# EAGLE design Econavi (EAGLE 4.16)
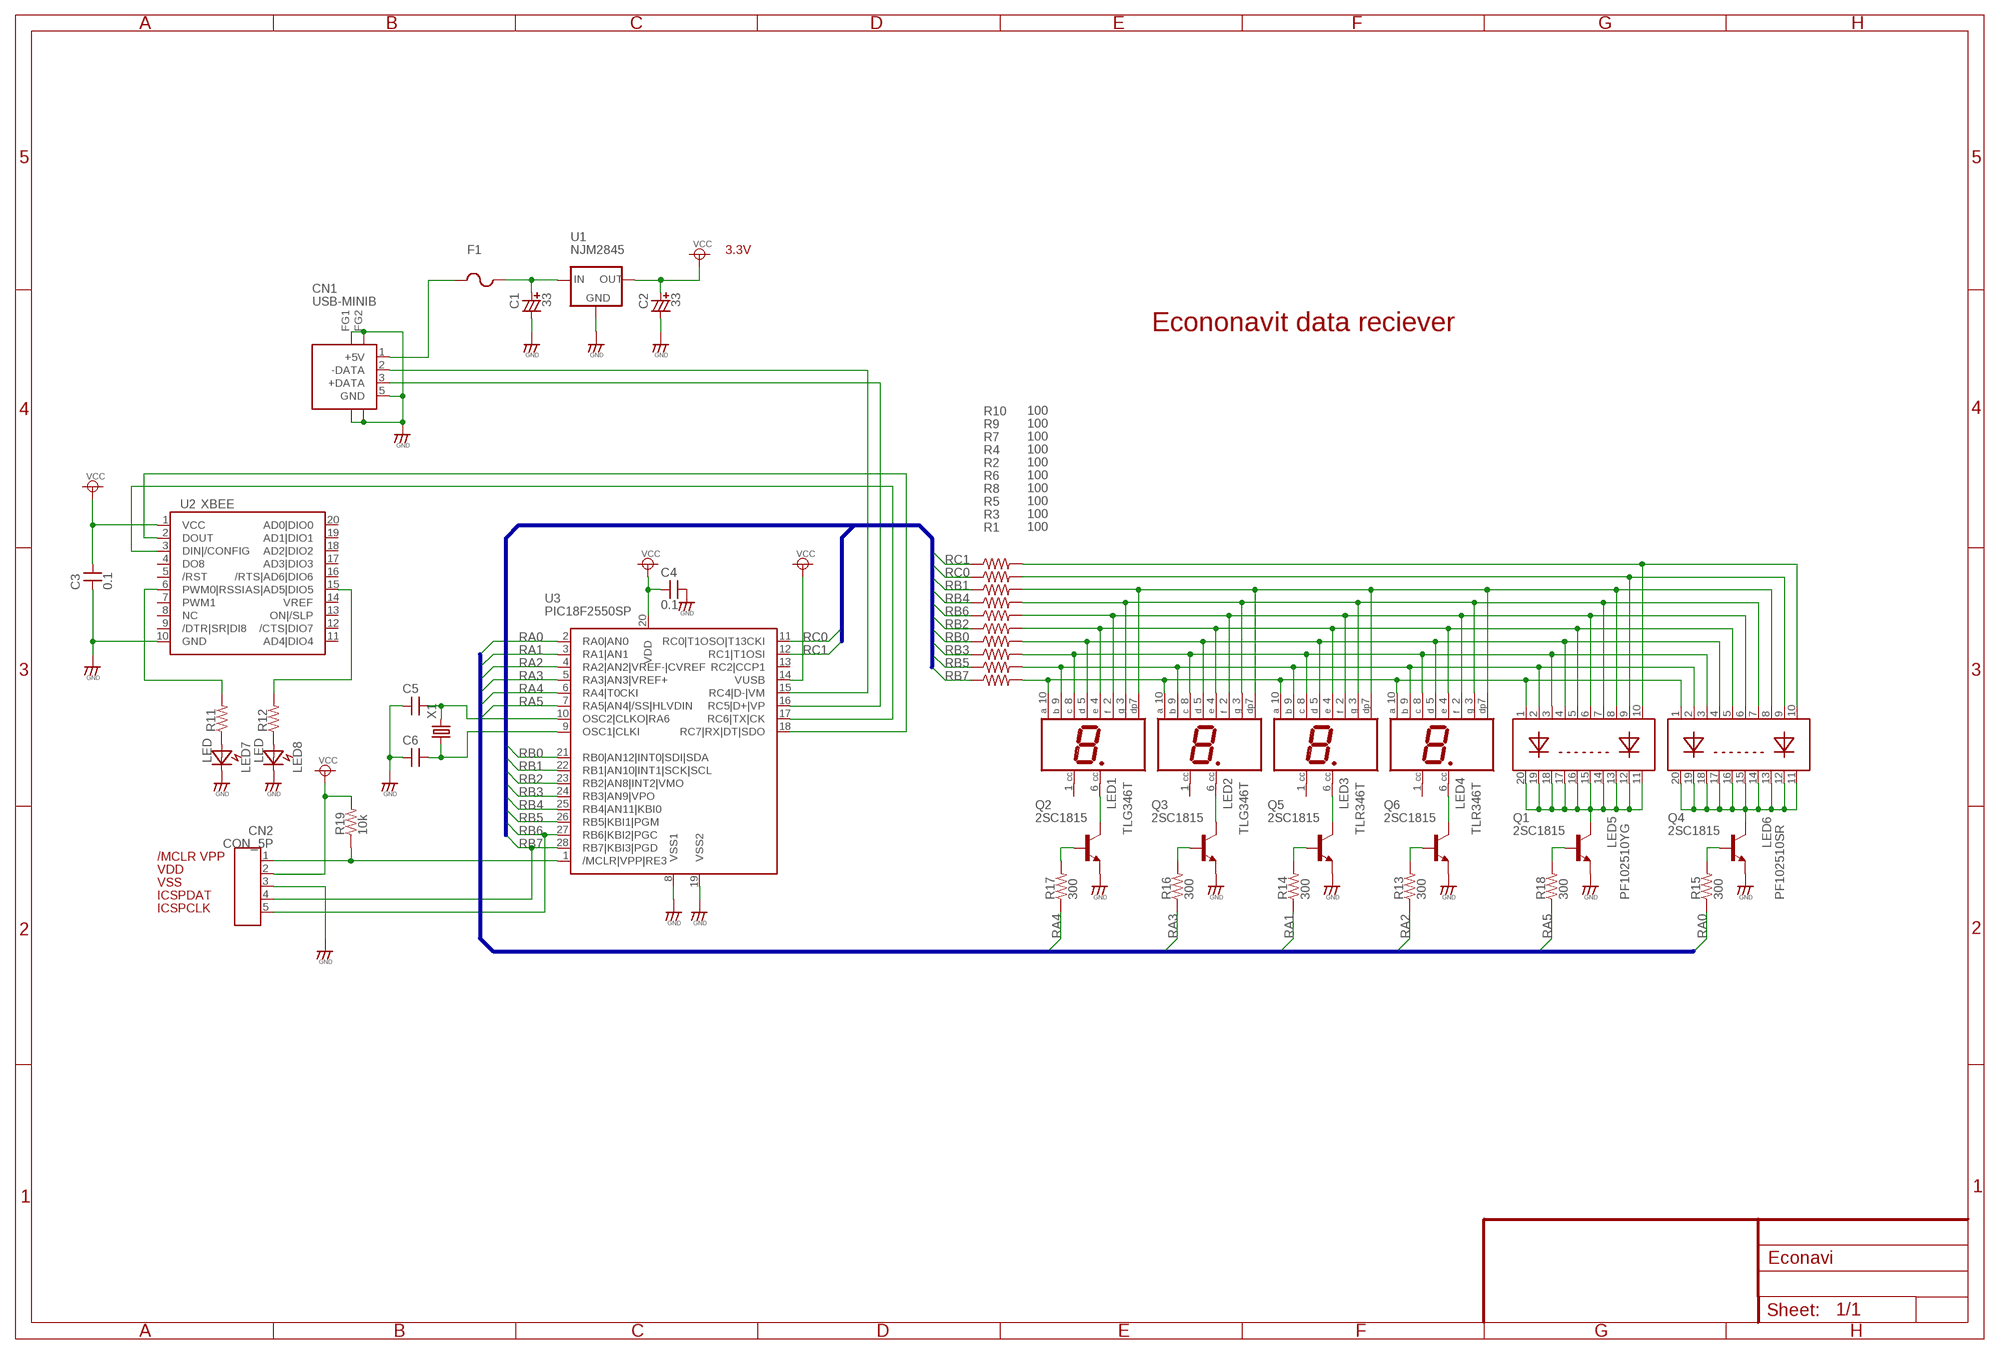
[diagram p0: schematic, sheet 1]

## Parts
C1  33  CCAPSMD3528  [CT3528]
C2  33  CCAPSMD3528  [CT3528]
C3  0.1  CAPSM2012  [C2012]
C4  0.1  CAPSM2012  [C2012]
C5  CAPDIP_1  [CAP_DIP_1]
C6  CAPDIP_1  [CAP_DIP_1]
CN1  USB-MINIB  [MINI-USB-B]
CN2  CON_5P  [CON_HDR_SIP5]
F1  POLYSW8X2MM  [AX_08X02_2P_200]
LED1  TLG346T  [4-10D1]
LED2  TLG346T  [4-10D1]
LED3  TLR346T  [4-10D1]
LED4  TLR346T  [4-10D1]
LED5  PF102510YG  PF102510  [LED10BAR]
LED6  PF102510SR  PF102510  [LED10BAR]
LED7  LED  [LED_3MM_VIRT_2]
LED8  LED  [LED_3MM_VIRT_2]
Q1  2SC1815  [TO92]
Q2  2SC1815  [TO92]
Q3  2SC1815  [TO92]
Q4  2SC1815  [TO92]
Q5  2SC1815  [TO92]
Q6  2SC1815  [TO92]
R1  100  R0.125W_2P  [R_0.125W_2]
R2  100  R0.125W_2P  [R_0.125W_2]
R3  100  R0.125W_2P  [R_0.125W_2]
R4  100  R0.125W_2P  [R_0.125W_2]
R5  100  R0.125W_2P  [R_0.125W_2]
R6  100  R0.125W_2P  [R_0.125W_2]
R7  100  R0.125W_2P  [R_0.125W_2]
R8  100  R0.125W_2P  [R_0.125W_2]
R9  100  R0.125W_2P  [R_0.125W_2]
R10  100  R0.125W_2P  [R_0.125W_2]
R11  R0.125W_2P  [R_0.125W_2]
R12  R0.125W_2P  [R_0.125W_2]
R13  300  R0.125W_2P  [R_0.125W_2]
R14  300  R0.125W_2P  [R_0.125W_2]
R15  300  R0.125W_2P  [R_0.125W_2]
R16  300  R0.125W_2P  [R_0.125W_2]
R17  300  R0.125W_2P  [R_0.125W_2]
R18  300  R0.125W_2P  [R_0.125W_2]
R19  10k  R0.125W_2P  [R_0.125W_2]
U1  NJM2845  [TO252]
U2  XBEE  [XBEE]
U3  PIC18F2550SP  [DIL28]
X1  CRYSTALHC49S  [HC49/S]

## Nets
DVCC: C2.+ C3.2 C4.1 CN2.2 R19.2 U1.3(OUT) U2.1(VCC) U3.14(VUSB) U3.20(VDD) ; supply symbol labelled VCC
GND: C1.- C2.- C3.1 C4.2 C5.1 C6.1 CN1.5(GND) CN1.FG1 CN1.FG2 CN1.FG3 CN1.FG4 CN2.3 LED7.K LED8.K Q1.E Q2.E Q3.E Q4.E Q5.E Q6.E U1.2(GND) U2.10(GND) U3.8(VSS1) U3.19(VSS2)
LED50: LED6.11(K9) LED6.12(K8) LED6.13(K7) LED6.14(K6) LED6.15(K5) LED6.16(K4) LED6.17(K3) LED6.18(K2) LED6.19(K1) LED6.20(K0) Q4.C
N$1: C1.+ F1.2 U1.1(IN)
N$2: LED1.6(CA) Q2.C
N$3: LED8.A R12.1
N$4: LED1.5(D) LED2.5(D) LED3.5(D) LED4.5(D) LED5.4(A3) LED6.4(A3) R8.2
N$5: LED5.11(K9) LED5.12(K8) LED5.13(K7) LED5.14(K6) LED5.15(K5) LED5.16(K4) LED5.17(K3) LED5.18(K2) LED5.19(K1) LED5.20(K0) Q1.C
N$6: LED1.2(F) LED2.2(F) LED3.2(F) LED4.2(F) LED5.6(A5) LED6.6(A5) R2.2
N$7: LED7.A R11.1
N$8: LED1.7(DP) LED2.7(DP) LED3.7(DP) LED4.7(DP) LED5.8(A7) LED6.8(A7) R7.2
N$9: LED1.10(A) LED2.10(A) LED3.10(A) LED4.10(A) LED5.1(A0) LED6.1(A0) R1.2
N$10: R12.2 U2.15(AS|AD5|DIO5)
N$11: R11.2 U2.6(PWM0|RSSI)
N$12: LED1.8(C) LED2.8(C) LED3.8(C) LED4.8(C) LED5.3(A2) LED6.3(A2) R5.2
N$13: U2.2(DOUT) U3.18(RC7|RX|DT|SDO)
N$14: LED1.4(E) LED2.4(E) LED3.4(E) LED4.4(E) LED5.5(A4) LED6.5(A4) R6.2
N$15: U2.3(DIN|/CONFIG) U3.17(RC6|TX|CK)
N$16: LED1.3(G) LED2.3(G) LED3.3(G) LED4.3(G) LED5.7(A6) LED6.7(A6) R4.2
N$17: CN1.2(-DATA) U3.15(RC4|D-|VM)
N$18: LED2.6(CA) Q3.C
N$19: Q6.B R13.2
N$20: LED3.6(CA) Q5.C
N$21: LED4.6(CA) Q6.C
N$22: Q5.B R14.2
N$23: Q4.B R15.2
N$24: Q3.B R16.2
N$25: CN1.3(+DATA) U3.16(RC5|D+|VP)
N$26: CN1.1(+5V) F1.1
N$27: LED1.9(B) LED2.9(B) LED3.9(B) LED4.9(B) LED5.2(A1) LED6.2(A1) R3.2
N$28: Q2.B R17.2
N$29: LED5.9(A8) LED6.9(A8) R9.2
N$30: Q1.B R18.2
N$31: CN2.1 R19.1 U3.1(/MCLR|VPP|RE3)
N$32: C5.2 U3.10(OSC2|CLKO|RA6) X1.2
N$33: LED5.10(A9) LED6.10(A9) R10.2
N$34: C6.2 U3.9(OSC1|CLKI) X1.1
RA0: R15.1 U3.2(RA0|AN0)
RA1: R14.1 U3.3(RA1|AN1)
RA2: R13.1 U3.4(RA2|AN2|VREF-|CVREF)
RA3: R16.1 U3.5(RA3|AN3|VREF+)
RA4: R17.1 U3.6(RA4|T0CKI)
RA5: R18.1 U3.7(RA5|AN4|/SS|HLVDIN)
RB0: R8.1 U3.21(RB0|AN12|INT0|SDI|SDA)
RB1: R7.1 U3.22(RB1|AN10|INT1|SCK|SCL)
RB2: R6.1 U3.23(RB2|AN8|INT2|VMO)
RB3: R5.1 U3.24(RB3|AN9|VPO)
RB4: R4.1 U3.25(RB4|AN11|KBI0)
RB5: R3.1 U3.26(RB5|KBI1|PGM)
RB6: CN2.5 R2.1 U3.27(RB6|KBI2|PGC)
RB7: CN2.4 R1.1 U3.28(RB7|KBI3|PGD)
RC0: R9.1 U3.11(RC0|T1OSO|T13CKI)
RC1: R10.1 U3.12(RC1|T1OSI)
Unconnected: LED1.1(CA) LED2.1(CA) LED3.1(CA) LED4.1(CA) U2.4(DO8) U2.5(/RST) U2.7(PWM1) U2.8(NC) U2.9(/DTR|SR|DI8) U2.11(AD4|DIO4) U2.12(/CTS|DIO7) U2.13(ON|/SLP) U2.14(VREF) U2.16(/RTS|AD6|DIO6) U2.17(AD3|DIO3) U2.18(AD2|DIO2) U2.19(AD1|DIO1) U2.20(AD0|DIO0) U3.13(RC2|CCP1)

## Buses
RB[0..7],RC[0..1]
RA[0..5]

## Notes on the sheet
- 3.3V
- Econonavit data reciever
- /MCLR VPP
- VDD
- VSS
- ICSPDAT
- ICSPCLK

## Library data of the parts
C1 C2 = Econavi:CCAP: Polar capacitor
C3-C6 = Econavi:CAP: Non polar capacitor
CN1 = WirelessTemp:USB-MINIB
CN2 = Econavi:CON_5P
F1 = Econavi:POLYSW
LED1 LED2 = Econavi:TLG346T: LED DISPLAY 1-character 7 segment, decimal point right
LED3 LED4 = Econavi:TLR346T
LED5 LED6 = Econavi:PF102510
LED7 LED8 = Econavi:LED
Q1-Q6 = Econavi:2SC1815: General use NPN transistor
R1-R19 = Econavi:R
U1 = Econavi:NJM2845
U2 = Econavi:XBEE
U3 = Econavi:PIC18F2550
X1 = Econavi:CRYSTAL: CRYSTAL

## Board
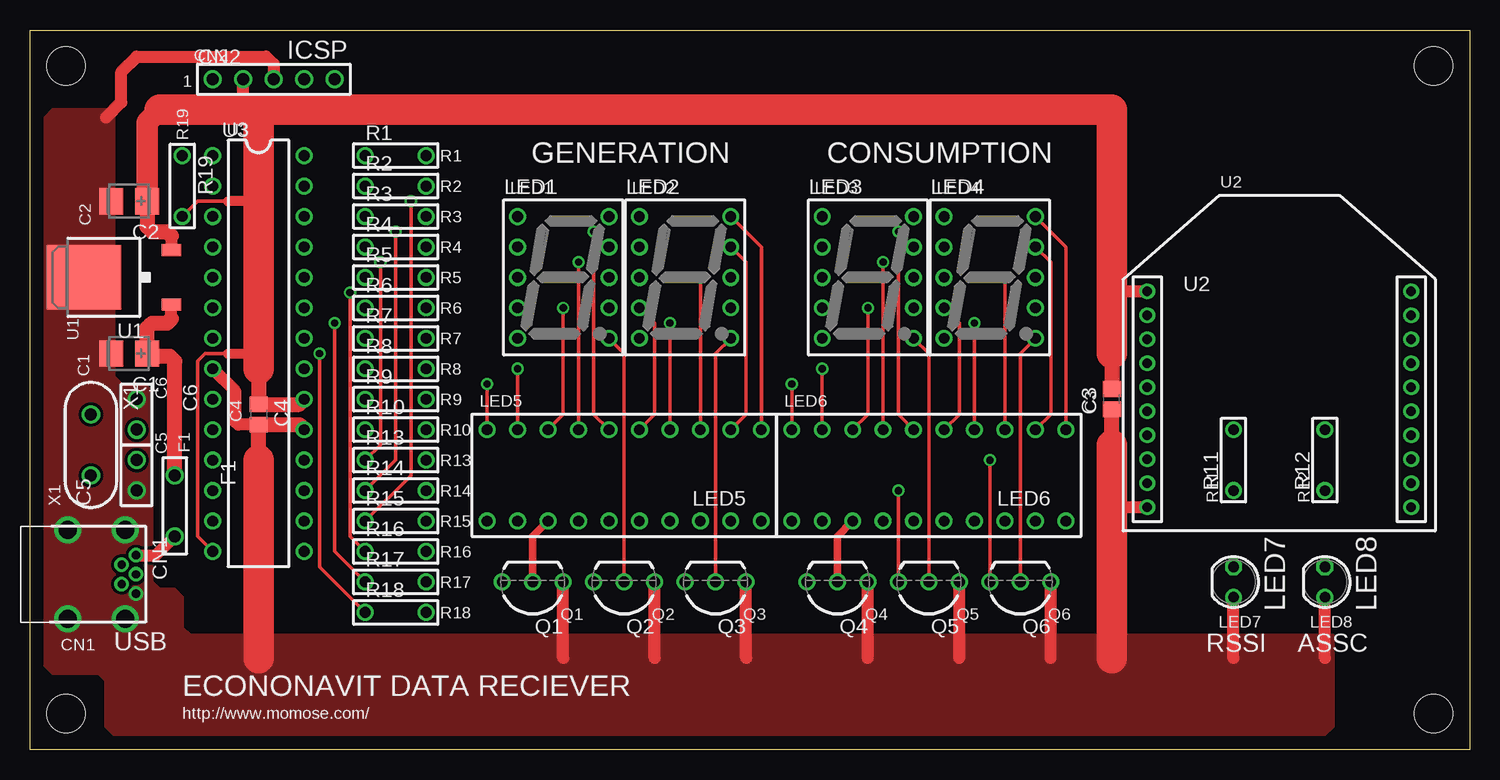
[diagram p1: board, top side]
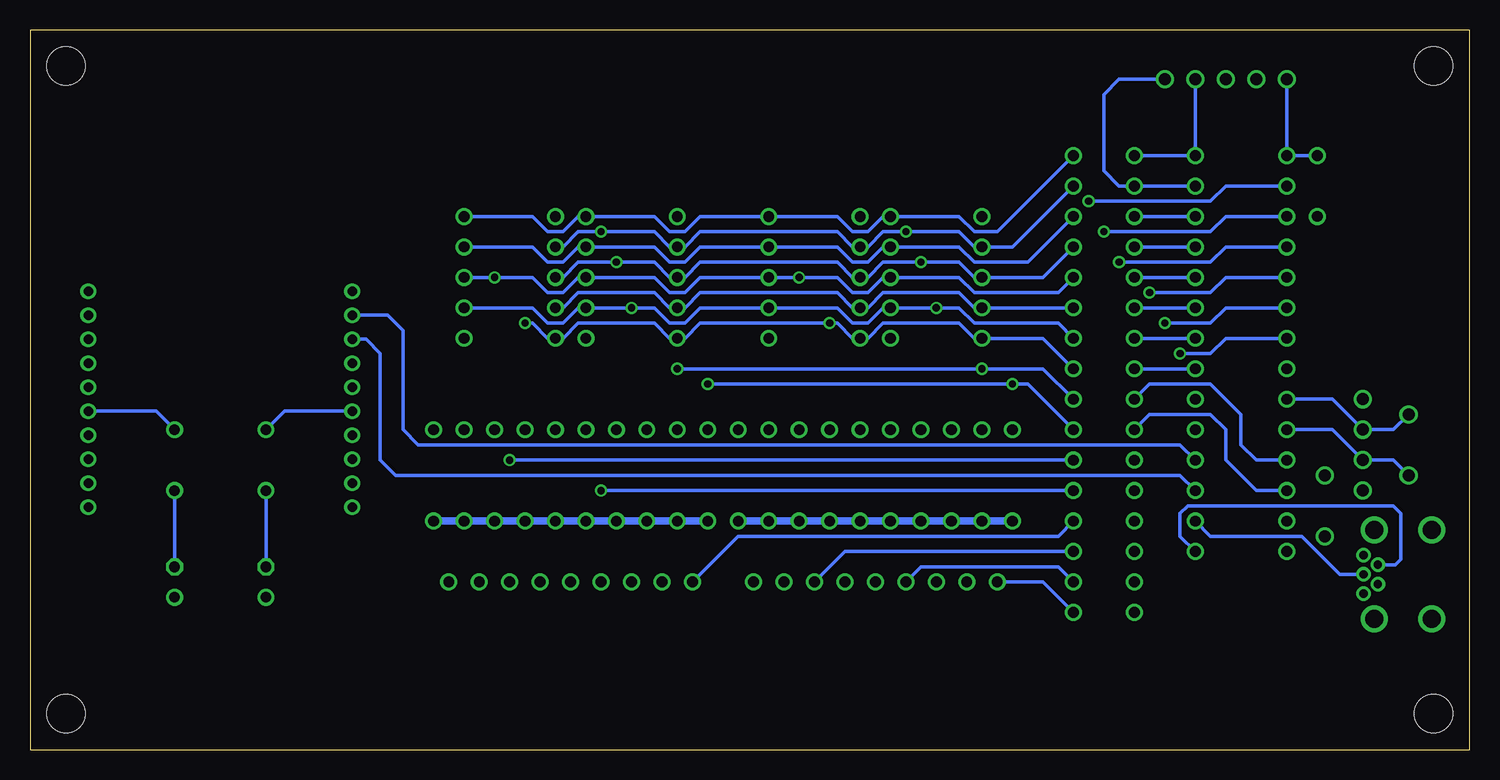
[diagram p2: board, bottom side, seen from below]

Size 120 x 60 mm. Coordinates in mm from the lower left corner, seen from the top.
Outline: 0,0 0,60 120,60 120,0 0,0
Copper layers (1*16): Top 0.035mm / dielectric 1.5mm / Bottom 0.035mm
Design rules "default": minimum track width 10mil, minimum drill 0.6mm, track to track 10mil, track to pad 10mil, pad to pad 10mil, via to via 10mil, smd to smd 8mil, copper to edge 40mil, drill to drill 8mil, minimum pad ring 10mil, minimum via ring 8mil, stop-mask expansion 4mil, vias tented up to drill 0mil, thermal gap 10mil
Holes 3.2 mm at 3,3 3,57 117,57 117,3

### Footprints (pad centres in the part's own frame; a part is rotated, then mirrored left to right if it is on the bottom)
CT3528 = smd 2 x 2.2: + -1.5,0; - 1.5,0
C2012 = smd 1.3 x 1.5: 1 -0.85,0; 2 0.85,0
CAP_DIP_1 = drill 1 round: 1 -1.27,0; 2 1.27,0
MINI-USB-B = drill 0.7 pad 1.118 round: 1 -1.6,4.4; 2 -0.8,3.2; 3 0,4.4; 4 0.8,3.2; 5 1.6,4.4 | drill 1.5 round: FG1 -3.7,3.5; FG2 3.7,3.5; FG3 -3.7,-1.3; FG4 3.7,-1.3
CON_HDR_SIP5 = drill 1 round: 1 -5.08,0; 2 -2.54,0; 3 0,0; 4 2.54,0; 5 5.08,0
AX_08X02_2P_200 = drill 1 round: 1 2.54,0; 2 -2.54,0
4-10D1 = drill 0.9 round: 1 -3.81,5.08; 2 -3.81,2.54; 3 -3.81,0; 4 -3.81,-2.54; 5 -3.81,-5.08; 6 3.81,-5.08; 7 3.81,-2.54; 8 3.81,0; 9 3.81,2.54; 10 3.81,5.08
LED10BAR = drill 0.9 round: 1 -10.16,-5.08; 2 -7.62,-5.08; 3 -5.08,-5.08; 4 -2.54,-5.08; 5 0,-5.08; 6 2.54,-5.08; 7 5.08,-5.08; 8 7.62,-5.08; 9 10.16,-5.08; 10 12.7,-5.08; 11 12.7,2.54; 12 10.16,2.54; 13 7.62,2.54; 14 5.08,2.54; 15 2.54,2.54; 16 0,2.54; 17 -2.54,2.54; 18 -5.08,2.54; 19 -7.62,2.54; 20 -10.16,2.54
LED_3MM_VIRT_2 = drill 0.9 octagon: A -1.27,0 | drill 0.9 round: K 1.27,0
TO92 = drill 0.9 round: B 2.54,0; C 0,0; E -2.54,0
R_0.125W_2 = drill 0.9 round: 1 -2.54,0; 2 2.54,0
TO252 = smd 1 x 1.6: 1 -2.28,-4.8; 3 2.28,-4.8 | smd 5.4 x 6.2: 2 0,2.5
XBEE = drill 0.8 round: 1 -11,9; 2 -11,7; 3 -11,5; 4 -11,3; 5 -11,1; 6 -11,-1; 7 -11,-3; 8 -11,-5; 9 -11,-7; 10 -11,-9; 11 11,-9; 12 11,-7; 13 11,-5; 14 11,-3; 15 11,-1; 16 11,1; 17 11,3; 18 11,5; 19 11,7; 20 11,9
DIL28 = drill 0.9 round: 1 -16.51,-3.81; 2 -13.97,-3.81; 3 -11.43,-3.81; 4 -8.89,-3.81; 5 -6.35,-3.81; 6 -3.81,-3.81; 7 -1.27,-3.81; 8 1.27,-3.81; 9 3.81,-3.81; 10 6.35,-3.81; 11 8.89,-3.81; 12 11.43,-3.81; 13 13.97,-3.81; 14 16.51,-3.81; 15 16.51,3.81; 16 13.97,3.81; 17 11.43,3.81; 18 8.89,3.81; 19 6.35,3.81; 20 3.81,3.81; 21 1.27,3.81; 22 -1.27,3.81; 23 -3.81,3.81; 24 -6.35,3.81; 25 -8.89,3.81; 26 -11.43,3.81; 27 -13.97,3.81; 28 -16.51,3.81
HC49/S = drill 1 round: 1 -2.54,0; 2 2.54,0

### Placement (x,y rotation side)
C1  8.26,33.02 180 top
C2  8.26,45.72 180 top
C3  90.17,29.21 90 top
C4  19.05,27.94 270 top
C5  8.89,22.86 90 top
C6  8.89,27.94 270 top
CN1  4.45,14.61 270 top
CN2  20.32,55.88 0 top
F1  12.06,20.32 270 top
LED1  44.45,39.37 0 top
LED2  54.61,39.37 0 top
LED3  69.85,39.37 0 top
LED4  80.01,39.37 0 top
LED5  50.8,21.59 180 top
LED6  76.2,21.59 180 top
LED7  100.33,13.97 270 top
LED8  107.95,13.97 270 top
Q1  41.91,13.97 180 top
Q2  49.53,13.97 180 top
Q3  57.15,13.97 180 top
Q4  67.31,13.97 180 top
Q5  74.93,13.97 180 top
Q6  82.55,13.97 180 top
R1  30.48,49.53 0 top
R2  30.48,46.99 0 top
R3  30.48,44.45 0 top
R4  30.48,41.91 0 top
R5  30.48,39.37 0 top
R6  30.48,36.83 0 top
R7  30.48,34.29 0 top
R8  30.48,31.75 0 top
R9  30.48,29.21 0 top
R10  30.48,26.67 0 top
R11  100.33,24.13 90 top
R12  107.95,24.13 90 top
R13  30.48,24.13 0 top
R14  30.48,21.59 0 top
R15  30.48,19.05 0 top
R16  30.48,16.51 0 top
R17  30.48,13.97 0 top
R18  30.48,11.43 0 top
R19  12.7,46.99 270 top
U1  6.99,39.37 90 top
U2  104.14,29.21 0 top
U3  19.05,33.02 270 top
X1  5.08,25.4 270 top

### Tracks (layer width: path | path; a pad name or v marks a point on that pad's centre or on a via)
DVCC
  Top 0.305: U3.14 13.97,17.78 13.97,32.38 14.61,33.02 16.51,33.02 | R19.2 13.97,45.72 16.51,45.72
  Top 0.813: 16.51,33.02 19.05,33.02 | 19.05,45.72 16.51,45.72
  Top 1.016: U2.1 90.28,38.21 90.17,38.1 | 17.78,53.34 CN2.2 | 11.79,42.83 U1.3
  Top 1.27: 90.17,33.02 C3.2 | 19.05,31.75 C4.1 22.44,28.79 U3.20 | 11.79,42.83 11.43,43.18 10.16,43.18 9.76,43.59 C2.+
  Top 1.778: C2.+ 9.76,52.3 10.79,53.34
  Top 2.54: 19.05,53.34 90.17,53.34 90.17,38.1 90.17,33.02 | 19.05,31.75 19.05,33.02 19.05,45.72 19.05,53.34 | 19.05,53.34 17.78,53.34 10.79,53.34
GND
  Top 1.016: 44.45,7.62 Q1.E | 52.07,7.62 Q2.E | 59.69,7.62 Q3.E | 69.85,7.62 Q4.E | 77.47,7.62 Q5.E | 85.09,7.62 Q6.E | 100.33,7.62 LED7.K | 107.95,7.62 LED8.K | U3.8 17.14,29.84 17.14,27.3 17.36,27.09 C4.2 | U2.10 90.28,20.21 90.17,20.32 | CN2.3 20.32,57.15 19.68,57.78 8.89,57.78 7.62,56.52 7.62,53.98 6.35,52.7
  Top 1.27: 90.17,25.4 C3.1 | 19.05,24.13 C4.2 22.44,27.09 U3.19
  Top 2.54: 90.17,7.62 90.17,20.32 90.17,25.4 | 19.05,7.62 19.05,24.13
  pour Top (no thermals): 1.91,53.34 1.27,52.7 1.27,6.99 1.91,6.35 5.71,6.35 6.35,5.71 6.35,1.91 6.99,1.27 107.95,1.27 108.58,1.91 108.58,9.53 13.34,9.53 12.7,10.16 12.7,12.7 12.06,13.34 10.79,13.34 10.16,13.97 10.16,29.84 9.53,30.48 7.62,30.48 6.99,31.11 6.99,52.7 6.35,53.34
LED50
  Top 0.61: Q4.C 67.31,17.78 LED6.13
  Bottom 0.61: LED6.11 LED6.12 LED6.13 LED6.14 LED6.15 LED6.16 LED6.17 LED6.18 LED6.19 LED6.20
N$1
  Top 1.016: 11.79,35.91 U1.1
  Top 1.27: 11.79,35.91 11.43,35.56 10.16,35.56 9.76,35.16 C1.+ 9.76,32.79 11.66,32.79 12.06,32.38 F1.2
N$2
  Top 0.305: LED1.6 49.53,33.02 Q2.C
N$3
  Bottom 0.305: LED8.A R12.1
N$4  (via drill 0.6)
  Top 0.305: v78.74,35.56 LED6.4 | v53.34,35.56 LED5.4
  Bottom 0.305: v78.74,35.56 78.11,35.56 76.83,34.29 LED4.5 75.56,34.29 74.3,35.56 67.94,35.56 66.67,34.29 LED3.5 65.41,34.29 64.14,35.56 v53.34,35.56 52.7,35.56 51.44,34.29 LED2.5 50.16,34.29 48.9,35.56 42.55,35.56 41.27,34.29 LED1.5 35.56,34.29 R8.2
N$5
  Top 0.61: Q1.C 41.91,17.78 LED5.13
  Bottom 0.61: LED5.11 LED5.12 LED5.13 LED5.14 LED5.15 LED5.16 LED5.17 LED5.18 LED5.19 LED5.20
N$6  (via drill 0.6)
  Top 0.305: LED6.6 72.39,27.94 v72.39,43.18 | LED5.6 46.99,27.94 v46.99,43.18
  Bottom 0.305: LED4.2 75.56,41.91 74.3,43.18 v72.39,43.18 67.94,43.18 66.67,41.91 LED3.2 65.41,41.91 64.14,43.18 52.7,43.18 51.44,41.91 LED2.2 50.16,41.91 48.9,43.18 v46.99,43.18 42.55,43.18 41.27,41.91 LED1.2 38.1,41.91 R2.2
N$7
  Bottom 0.305: LED7.A R11.1
N$8  (via drill 0.6)
  Top 0.305: v69.85,36.83 69.85,27.94 LED6.8 | LED5.8 44.45,27.94 v44.45,36.83
  Bottom 0.305: LED4.7 78.11,36.83 76.83,35.56 75.56,35.56 74.3,36.83 LED3.7 v69.85,36.83 67.94,36.83 66.67,35.56 65.41,35.56 64.14,36.83 LED2.7 52.7,36.83 51.44,35.56 50.16,35.56 48.9,36.83 LED1.7 v44.45,36.83 42.55,36.83 41.27,35.56 34.29,35.56 R7.2
N$9
  Top 0.305: LED6.1 86.36,41.91 LED4.10 | LED5.1 60.96,41.91 LED2.10
  Bottom 0.305: LED4.10 78.11,44.45 76.83,43.18 75.56,43.18 74.3,44.45 LED3.10 67.94,44.45 66.67,43.18 65.41,43.18 64.14,44.45 LED2.10 52.7,44.45 51.44,43.18 50.16,43.18 48.9,44.45 LED1.10 42.55,44.45 41.27,43.18 39.37,43.18 R1.2
N$10
  Bottom 0.305: U2.15 109.49,28.21 R12.2
N$11
  Bottom 0.305: U2.6 98.79,28.21 R11.2
N$12  (via drill 0.6)
  Top 0.305: v81.28,39.37 LED6.3 | v55.88,39.37 LED5.3
  Bottom 0.305: LED4.8 v81.28,39.37 78.11,39.37 76.83,38.1 75.56,38.1 74.3,39.37 LED3.8 67.94,39.37 66.67,38.1 65.41,38.1 64.14,39.37 LED2.8 v55.88,39.37 52.7,39.37 51.44,38.1 50.16,38.1 48.9,39.37 LED1.8 42.55,39.37 41.27,38.1 34.29,38.1 R5.2
N$13
  Bottom 0.305: U3.18 24.13,25.4 87.63,25.4 88.9,26.67 88.9,34.92 90.19,36.21 U2.2
N$14
  Top 0.305: LED5.5 52.07,27.94 52.07,35.56 LED2.4 | LED6.5 77.47,27.94 77.47,35.56 LED4.4
  Bottom 0.305: LED4.4 75.56,36.83 74.3,38.1 67.94,38.1 66.67,36.83 LED3.4 65.41,36.83 64.14,38.1 52.7,38.1 51.44,36.83 LED2.4 50.16,36.83 48.9,38.1 42.55,38.1 41.27,36.83 LED1.4 R6.2
N$15
  Bottom 0.305: U3.17 24.13,22.86 89.53,22.86 90.81,24.13 90.81,33.02 92,34.21 U2.3
N$16  (via drill 0.6)
  Top 0.305: v71.12,40.64 LED6.7 | LED5.7 v45.72,40.64
  Bottom 0.305: LED4.3 75.56,39.37 74.3,40.64 v71.12,40.64 67.94,40.64 66.67,39.37 LED3.3 65.41,39.37 64.14,40.64 52.7,40.64 51.44,39.37 LED2.3 50.16,39.37 48.9,40.64 v45.72,40.64 42.55,40.64 41.27,39.37 LED1.3 35.56,39.37 R4.2
N$17
  Bottom 0.305: U3.15 24.13,17.78 24.13,19.68 23.5,20.32 6.35,20.32 5.71,19.68 5.71,15.88 6.18,15.4 CN1.2
N$18
  Top 0.305: LED2.6 57.15,33.02 Q3.C
N$19  (via drill 0.6)
  Top 0.305: v80.01,24.13 Q6.B
  Bottom 0.305: R13.2 v80.01,24.13
N$20
  Top 0.305: LED3.6 74.93,33.02 Q5.C
N$21
  Top 0.305: LED4.6 82.55,33.02 Q6.C
N$22  (via drill 0.6)
  Top 0.305: v72.39,21.59 Q5.B
  Bottom 0.305: R14.2 v72.39,21.59
N$23
  Bottom 0.305: R15.2 34.29,17.78 60.96,17.78 Q4.B
N$24
  Bottom 0.305: R16.2 52.07,16.51 Q3.B
N$25
  Bottom 0.305: U3.16 21.59,17.78 13.97,17.78 10.79,14.61 CN1.3
N$26
  Top 1.016: CN1.1 10.49,16.2 F1.1
N$27
  Top 0.305: LED5.2 59.69,27.94 59.69,40.64 LED2.9 | LED4.9 85.09,40.64 85.09,27.94 LED6.2
  Bottom 0.305: LED4.9 78.11,41.91 76.83,40.64 75.56,40.64 74.3,41.91 LED3.9 67.94,41.91 66.67,40.64 65.41,40.64 64.14,41.91 LED2.9 52.7,41.91 51.44,40.64 50.16,40.64 48.9,41.91 LED1.9 42.55,41.91 41.27,40.64 36.83,40.64 R3.2
N$28
  Bottom 0.305: R17.2 34.29,15.24 45.72,15.24 Q2.B
N$29  (via drill 0.6)
  Top 0.305: v66.04,31.75 LED6.9 | v40.64,31.75 LED5.9
  Bottom 0.305: v66.04,31.75 v40.64,31.75 35.56,31.75 R9.2
N$30
  Bottom 0.305: R18.2 35.56,13.97 Q1.B
N$31
  Bottom 0.305: CN2.1 U3.1 R19.1
N$32
  Bottom 0.305: X1.2 6.35,24.13 C5.2 11.43,26.67 U3.10
N$33  (via drill 0.6)
  Top 0.305: v63.5,30.48 LED6.10 | v38.1,30.48 LED5.10
  Bottom 0.305: v63.5,30.48 v38.1,30.48 36.83,30.48 R10.2
N$34
  Bottom 0.305: X1.1 6.35,26.67 C6.2 11.43,29.21 U3.9
RA0  (via drill 0.6)
  Top 0.305: v31.75,45.72 31.75,22.86 R15.1
  Bottom 0.305: U3.2 20.32,46.99 21.59,45.72 v31.75,45.72
RA1  (via drill 0.6)
  Top 0.305: v30.48,43.18 30.48,24.13 R14.1
  Bottom 0.305: U3.3 20.32,44.45 21.59,43.18 v30.48,43.18
RA2  (via drill 0.6)
  Top 0.305: v29.21,40.64 29.21,25.4 R13.1
  Bottom 0.305: U3.4 20.32,41.91 21.59,40.64 v29.21,40.64
RA3  (via drill 0.6)
  Top 0.305: v26.67,38.1 26.67,17.78 R16.1
  Bottom 0.305: U3.5 20.32,39.37 21.59,38.1 v26.67,38.1
RA4  (via drill 0.6)
  Top 0.305: v25.4,35.56 25.4,16.51 R17.1
  Bottom 0.305: U3.6 20.32,36.83 21.59,35.56 v25.4,35.56
RA5  (via drill 0.6)
  Top 0.305: v24.13,33.02 24.13,15.24 R18.1
  Bottom 0.305: U3.7 20.32,34.29 21.59,33.02 v24.13,33.02
RB0
  Bottom 0.305: U3.21 R8.1
RB1
  Bottom 0.305: U3.22 R7.1
RB2
  Bottom 0.305: U3.23 R6.1
RB3
  Bottom 0.305: U3.24 R5.1
RB4
  Bottom 0.305: U3.25 R4.1
RB5
  Bottom 0.305: U3.26 R3.1
RB6
  Bottom 0.305: U3.27 R2.1 29.21,46.99 30.48,48.26 30.48,54.61 29.21,55.88 CN2.5
RB7
  Bottom 0.305: R1.1 U3.28 CN2.4
RC0
  Bottom 0.305: R9.1 26.67,30.48 21.59,30.48 19.05,27.94 19.05,25.4 17.78,24.13 U3.11
RC1
  Bottom 0.305: R10.1 26.67,27.94 21.59,27.94 20.32,26.67 20.32,24.13 17.78,21.59 U3.12

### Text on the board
Document: 60 | 120 | Econonavit reciever
_tPlace: RSSI | ASSC
_tNames: CN2 | ICSP | 1 | R19 | U3 | R1 | GENERATION | CONSUMPTION | U2 | R2 | LED1 | LED2 | LED3 | LED4 | C2 | R3 | R4 | R5 | U1 | R6 | R7 | C1 | R8 | C6 | R9 | LED5 | LED6 | C3 | C4 | R10 | C5 | F1 | R13 | R14 | R11 | R12 | X1 | R15 | R16 | R17 | R18 | Q1 | Q2 | Q3 | Q4 | Q5 | Q6 | LED7 | LED8 | CN1 | USB | ECONONAVIT DATA RECIEVER | http://www.momose.com/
